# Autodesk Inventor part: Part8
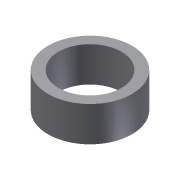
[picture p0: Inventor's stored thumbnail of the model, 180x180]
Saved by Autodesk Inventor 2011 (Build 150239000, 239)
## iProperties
Shininess: 77.0
Length Units: 11269
Angle Units: 11279
Time Units: 11290
Mass Units: 11283
Length Display Precision: 3
Angle Display Precision: 2
Created: 2002-01
Part Number: Part8
Document SubType Name: Modeling
Designer: ***
Density: 1 g/cm^3
Density: 0.0
Volumn: 0.0
Area: 0.0
PropertySet Name: Model Information
Control State: 0
Master: False
Checked Out: False
Author: ***
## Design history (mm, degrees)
sketch "Sketch1"
  geometry: C1 r 30 at (0, 0); C2 r 22.5 at (0, 0)
  constraints: 2 centre point, 1 coincident
  dimensions: "d0" = 60 diameter of C1; "d1" = 45 diameter of C2
extrude "Extrusion1" new body sketch "Sketch1" distance "d2" = 25; taper "d3" = 0 deg
body "Solid1"
